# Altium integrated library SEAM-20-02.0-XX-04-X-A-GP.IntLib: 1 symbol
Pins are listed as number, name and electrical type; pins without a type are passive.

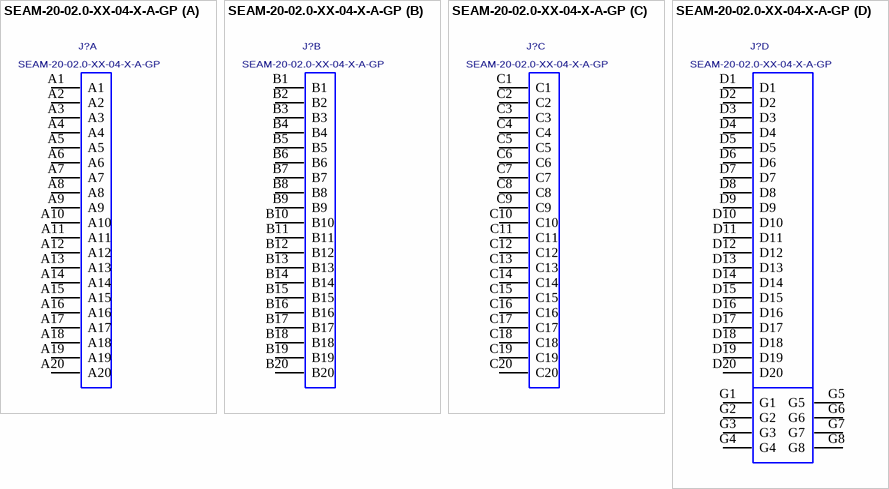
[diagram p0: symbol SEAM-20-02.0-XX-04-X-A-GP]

## SEAM-20-02.0-XX-04-X-A-GP
designator J?
0.050" TERMINAL ARRAY ASSEMBLY; MANUFACTURER: SAMTEC
footprint SEAM-20-02.0-XX-04-X-A-GP
part A pins: A1, A2, A3, A4, A5, A6, A7, A8, A9, A10, A11, A12, A13, A14, A15, A16, A17, A18, A19, A20
part B pins: B1, B2, B3, B4, B5, B6, B7, B8, B9, B10, B11, B12, B13, B14, B15, B16, B17, B18, B19, B20
part C pins: C1, C2, C3, C4, C5, C6, C7, C8, C9, C10, C11, C12, C13, C14, C15, C16, C17, C18, C19, C20
part D pins: D1, D2, D3, D4, D5, D6, D7, D8, D9, D10, D11, D12, D13, D14, D15, D16, D17, D18, D19, D20, G1, G2, G3, G4, G5, G6, G7, G8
